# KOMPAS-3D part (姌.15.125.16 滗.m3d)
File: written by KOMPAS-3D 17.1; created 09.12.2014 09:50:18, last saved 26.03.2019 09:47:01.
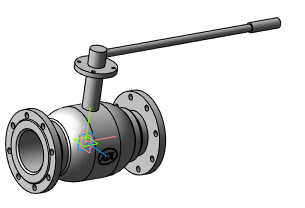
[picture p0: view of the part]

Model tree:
1. Операция без истории:5  (labels: Сталь 20  ГОСТ 1050-88)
